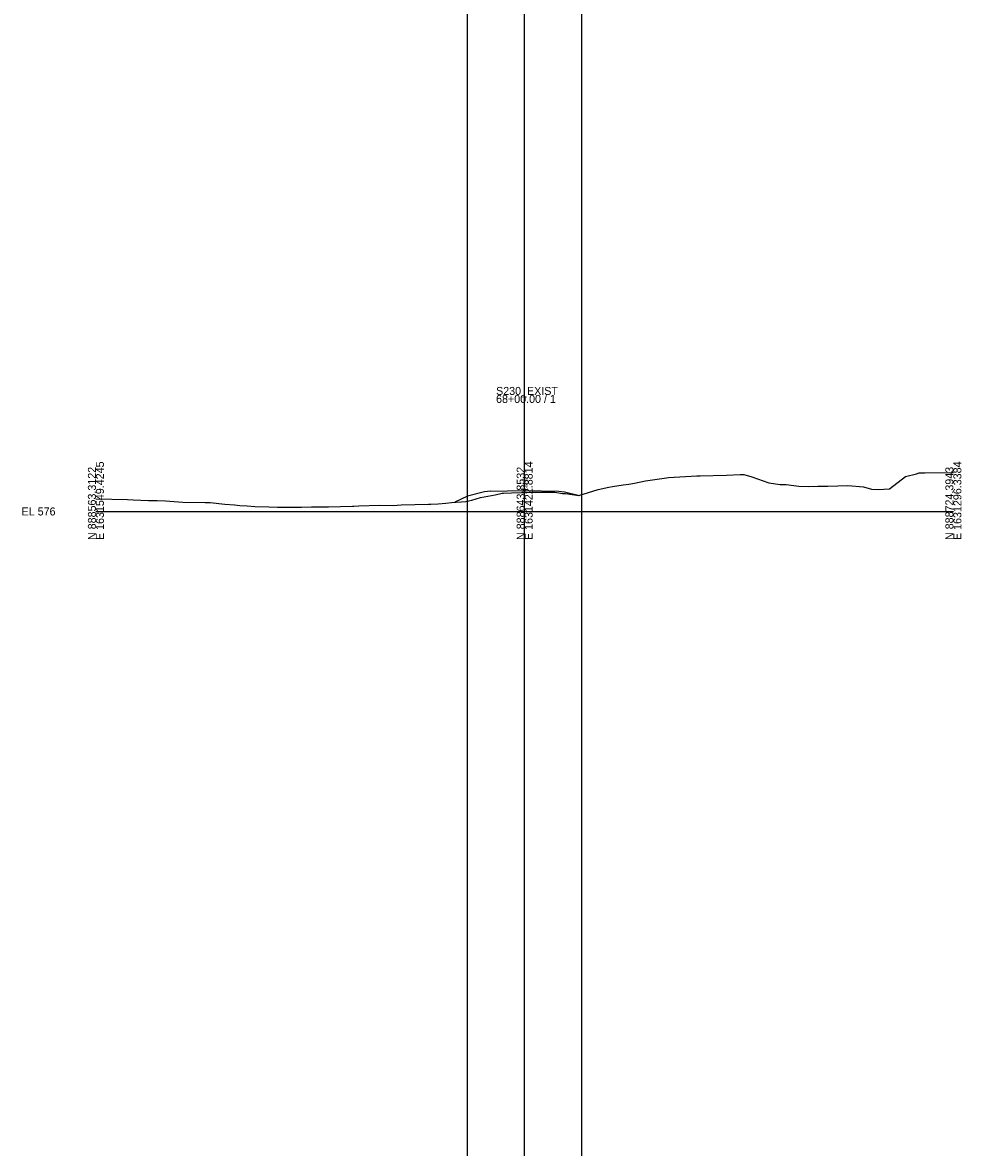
# Model space of a CAD drawing. Extents: x 1631115 to 1631443, y 885974 to 892071.
# Drawn here: x 1631114.8 to 1631443.3, y 886761.1 to 887154.7 of the extents above; entities that cross this region are included whole.
import ezdxf

# ---------------------------------------------------------------- set-up
doc = ezdxf.new("R2010")
doc.units = 0
for name, color, linetype in [('Default', 7, 'Continuous'), ('RD_GPK_XS_Cell', 7, 'Continuous'), ('RD_XS_EarthShd', 7, 'Continuous'), ('RD_XS_ExGround', 7, 'Continuous'), ('RD_XS_Pave', 7, 'Continuous'), ('RD_XS_TieSlope', 7, 'Continuous'), ('RD_XS_TX_Elev_EX', 7, 'Continuous'), ('RD_XS_TX_Elev_PR', 7, 'Continuous')]:
    doc.layers.add(name, color=color, linetype=linetype)

msp = doc.modelspace()

# ---------------------------------------------------------------- linework, layer by layer
at = {"layer": 'Default'}
for p, q in [((1631270.47, 885983.65), (1631270.47, 892068.63)), ((1631290.47, 885983.65), (1631290.47, 892068.63)), ((1631310.47, 885983.65), (1631310.47, 892068.63))]:
    msp.add_line(p, q, dxfattribs=at)
at = {"layer": 'RD_GPK_XS_Cell'}
for p, q in [((1631290.47, 886983.65), (1631290.47, 887024.41)), ((1631140.47, 886983.65), (1631290.47, 886983.65)), ((1631290.47, 886983.65), (1631440.47, 886983.65))]:
    msp.add_line(p, q, dxfattribs=at)
at = {"layer": 'RD_XS_EarthShd'}
for p, q in [((1631278.47, 886990.7), (1631276.47, 886990.54)), ((1631302.47, 886990.7), (1631304.47, 886990.54))]:
    msp.add_line(p, q, dxfattribs=at)
at = {"layer": 'RD_XS_ExGround'}
msp.add_lwpolyline([(1631140.47, 886988.05), (1631151.57, 886987.86), (1631153.54, 886987.72), (1631158.92, 886987.53), (1631159.44, 886987.49), (1631161.91, 886987.47), (1631164.85, 886987.35), (1631170.89, 886986.93), (1631178.68, 886986.75), (1631180.44, 886986.73), (1631185.52, 886986.23), (1631188.98, 886985.93), (1631190.83, 886985.78), (1631193.36, 886985.58), (1631196.09, 886985.4), (1631200.92, 886985.3), (1631204.02, 886985.15), (1631207.44, 886985.16), (1631212.41, 886985.18), (1631215.86, 886985.29), (1631221.48, 886985.22), (1631221.82, 886985.21), (1631230.22, 886985.49), (1631230.75, 886985.49), (1631232.4, 886985.6), (1631239.54, 886985.85), (1631244.46, 886985.75), (1631247.25, 886985.93), (1631256.84, 886986.23), (1631257.68, 886986.16), (1631260.26, 886986.29), (1631262.89, 886986.52), (1631264.88, 886986.76), (1631269.93, 886987.08), (1631272.02, 886987.65), (1631275.02, 886988.51), (1631280.12, 886989.49), (1631282.56, 886990.02), (1631283.07, 886990.04), (1631285.83, 886990.18), (1631289.51, 886990.31), (1631290.48, 886990.32), (1631293.26, 886990.37), (1631294.28, 886990.36), (1631299.11, 886990.41), (1631300.98, 886990.41), (1631303.66, 886989.97), (1631304.76, 886989.93), (1631309.42, 886989.19), (1631316.21, 886991.37), (1631319.9, 886992.15), (1631321.24, 886992.37), (1631324.91, 886992.92), (1631326.92, 886993.2), (1631328.94, 886993.53), (1631332.79, 886994.3), (1631340.11, 886995.41), (1631340.77, 886995.49), (1631350.74, 886996.12), (1631351.37, 886996.13), (1631351.85, 886996.16), (1631361.05, 886996.37), (1631365.84, 886996.56), (1631367.19, 886996.63), (1631369.93, 886995.8), (1631375.95, 886993.6), (1631379.82, 886993.05), (1631382, 886993.13), (1631386.4, 886992.44), (1631389.73, 886992.33), (1631393.06, 886992.44), (1631396.58, 886992.47), (1631403.53, 886992.71), (1631409.05, 886992.26), (1631411.87, 886991.41), (1631414.12, 886991.3), (1631418.18, 886991.61), (1631423.71, 886995.9), (1631427.55, 886996.76), (1631428.48, 886997.11), (1631430.54, 886997.21), (1631440.03, 886997.22), (1631440.47, 886997.24)], dxfattribs=at)
at = {"layer": 'RD_XS_Pave'}
for p, q in [((1631278.47, 886990.7), (1631290.47, 886990.94)), ((1631290.47, 886990.94), (1631302.47, 886990.7))]:
    msp.add_line(p, q, dxfattribs=at)
at = {"layer": 'RD_XS_TieSlope'}
for p, q in [((1631276.47, 886990.54), (1631270.47, 886989.04)), ((1631304.47, 886990.54), (1631309.61, 886989.25)), ((1631270.47, 886989.04), (1631266.08, 886986.84))]:
    msp.add_line(p, q, dxfattribs=at)

# ---------------------------------------------------------------- texts
at = {"layer": 'RD_GPK_XS_Cell'}
for s, p in [('S230_EXIST', (1631280.47, 887024.41)), ('68+00.00 / 1', (1631280.47, 887021.61)), ('EL 576', (1631114.47, 886982.25))]:
    msp.add_text(s, height=2.8, dxfattribs=at).set_placement(p)
for s, p in [('N 888563.3122', (1631140.47, 886973.65)), ('E 1631549.4245', (1631143.27, 886973.65)), ('N 888643.8532', (1631290.47, 886973.65)), ('E 1631422.8814', (1631293.27, 886973.65)), ('N 888724.3943', (1631440.47, 886973.65)), ('E 1631296.3384', (1631443.27, 886973.65))]:
    msp.add_text(s, height=2.8, rotation=90, dxfattribs=at).set_placement(p)
at = {"layer": 'RD_XS_TX_Elev_EX'}
msp.add_text('582.67', height=1, rotation=90, dxfattribs=at).set_placement((1631290.37, 886990.42))
at = {"layer": 'RD_XS_TX_Elev_PR'}
msp.add_text(' 583.28', height=1, rotation=90, dxfattribs=at).set_placement((1631291.47, 886990.94))

doc.saveas('drawing.dxf')
